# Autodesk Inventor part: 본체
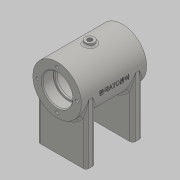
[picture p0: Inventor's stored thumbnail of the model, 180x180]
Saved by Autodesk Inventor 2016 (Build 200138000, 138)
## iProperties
Created: 2020-07
Part Number: 본체
Material: Generic
Document SubType Name: Modeling
Designer: user
Density: 1 g/cm^3
Appearance: Default
Author: user
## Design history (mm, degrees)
sketch "스케치1"
  geometry: C1 r 26 at (0, 0); 1 further point
  constraints: 1 centre point, 1 coincident
  dimensions: "d0" = 52 diameter of C1
extrude "돌출1" new body sketch "스케치1" stored distance "d1" = 70; taper "d2" = 0 deg
hole "구멍1" diameter "d5" = 28; stored, may be unused: countersink angle "d9" = 90 deg, drill point angle "d11" = 0 deg; dims "d6" = 6.35, "d7" = 32, "d8" = 12, "d10" = 14, "d12" = 10, "d13" = 10
hole "구멍2" diameter "d16" = 42; stored, may be unused: countersink angle "d20" = 90 deg, drill point angle "d22" = 0 deg; dims "d14" = 10, "d15" = 10, "d17" = 6.35, "d18" = 32, "d19" = 12, "d21" = 42
fillet "모깎기1" dims "d23" = 3
fillet "모깎기2" dims "d24" = 0.3
node "작업 평면1"
sketch "스케치2"
  geometry: L1 (-26, 0)-(-26, -64); L2 (-26, -64)-(26, -64); L3 (26, -64)-(26, 0); C1 r 20.236 at (0, 0) reference; A1 r 26 centre (0, 0) between (-26, 0) and (26, 0) reference; 1 further point
  constraints: 6 end point, 2 perpendicular, 2 point on circle, 2 tangent, 1 vertical
  dimensions: "d26" = 64 distance from line of point (0, 0) L2; "d27" = 52 distance of L1.end L2.end (derived)
extrude "돌출2" join sketch "스케치2" distance "d28" = 10; taper "d29" = 0 deg
fillet "모깎기3" dims "d30" = 3
fillet "모깎기4" dims "d31" = 3
sketch "스케치3" dims "d32" = 42
  geometry: L1 (0, 0)-(0, 21); C1 r 26 at (0, 0) reference; 1 further point
  constraints: 2 end point, 1 coincident, 1 vertical, 1 vertical alignment, 2 other
hole "구멍3" sketch "스케치3" at (0, 21) diameter "d33" = 3.242; stored, may be unused: countersink angle "d37" = 90 deg, drill point angle "d39" = 118 deg; dims "d34" = 8, "d35" = 32, "d36" = 12, "d38" = 10
node "작업 평면2"
sketch "스케치4"
  geometry: L1 (-26, -35)-(26, -35) reference; L2 (-26, -35)-(-26, 35) reference; 2 further points
  constraints: 1 coincident, 1 other
feature "엠보싱1" sketch "스케치4" dims "d46" = 0.5, "d47" = 0
sketch "스케치5"
  geometry: L1 (-26.429, 1.943)-(-25.93, 1.906) reference; L2 (-25.952, 1.576)-(-26.451, 1.606) reference; L3 (0, 0)-(0, -26); L4 (0, 0)-(9.919, -27.251); C1 r 21 at (0, 0) reference; A1 r 26.5 centre (0, 0) between (-26.429, 1.943) and (-26.451, 1.606) reference; A2 r 26 centre (0, 0) between (-25.952, 1.576) and (-25.93, 1.906) reference; 1 further point
  constraints: 4 end point, 1 point on circle, 1 vertical
  dimensions: "d48" = 29 distance of L3.start L4.end; "d49" = 20 deg angle of L4 L3
  node "절단 모서리 투영2"
node "작업 평면3"
sketch "스케치6"
  geometry: C1 r 6 at (0, 0); 1 further point
  constraints: 1 centre point, 1 coincident
  dimensions: "d50" = 12 diameter of C1
extrude "돌출3" join sketch "스케치6" stored distance "d51" = 10; taper "d52" = 0 deg
hole "구멍4" diameter "d55" = 5.188; stored, may be unused: countersink angle "d59" = 90 deg, drill point angle "d61" = 0 deg; dims "d53" = 10, "d54" = 10, "d56" = 12, "d57" = 32, "d58" = 12, "d60" = 16
fillet "모깎기5" dims "d62" = 2
node "작업 평면4"
sketch "스케치7"
  geometry: C1 r 5 at (0, 0); 1 further point
  constraints: 1 centre point, 1 coincident
  dimensions: "d64" = 10 diameter of C1
extrude "돌출4" join sketch "스케치7" stored distance "d65" = 10; taper "d66" = 0 deg
hole "구멍5" diameter "d69" = 5.188; stored, may be unused: countersink angle "d73" = 90 deg, drill point angle "d75" = 0 deg; dims "d67" = 10, "d68" = 10, "d70" = 12, "d71" = 32, "d72" = 12, "d74" = 16
fillet "모깎기6" dims "d76" = 2
sketch "스케치8"
  geometry: L1 (0, -10)-(46, -10) reference; L2 (49, -3)-(49, -7) reference; L3 (0, 0)-(46, 0) reference; L4 (-3, -3)-(-3, -7) reference; L5 (-3, -5)-(49, -5); A1 r 3 centre (0, -7) between (-3, -7) and (0, -10) reference; A2 r 3 centre (46, -7) between (46, -10) and (49, -7) reference; A3 r 3 centre (46, -3) between (49, -3) and (46, 0) reference; A4 r 3 centre (0, -3) between (0, 0) and (-3, -3) reference; 3 further points
  constraints: 2 end point, 2 midpoint, 2 point on line
  dimensions: "d77" = 5 distance between parallel lines of L5 L3 (derived); "d78" = 20 horizontal distance of point (3, -5) point (23, 20); "d79" = 40 distance of point (43, -5) point (3, -5)
hole "구멍6" sketch "스케치8" at (3, -5), (43, -5) diameter "d80" = 4.134; stored, may be unused: countersink angle "d84" = 90 deg, drill point angle "d86" = 118 deg; dims "d81" = 8, "d82" = 32, "d83" = 12, "d85" = 10
chamfer "모따기1" distance "d87" = 1; stored, may be unused: second distance "d88" = 2, angle "d89" = 45 deg
node "솔리드1"
mirror "대칭1"
mirror "대칭2"
pattern_circular "원형 패턴1" dims angle "d41" = 360 deg
mirror "대칭3"
mirror "대칭4"
node "투영된 루프1"
node "절단 모서리 투영1"
other parameters: "d43" = -35.5, "d63" = 29
